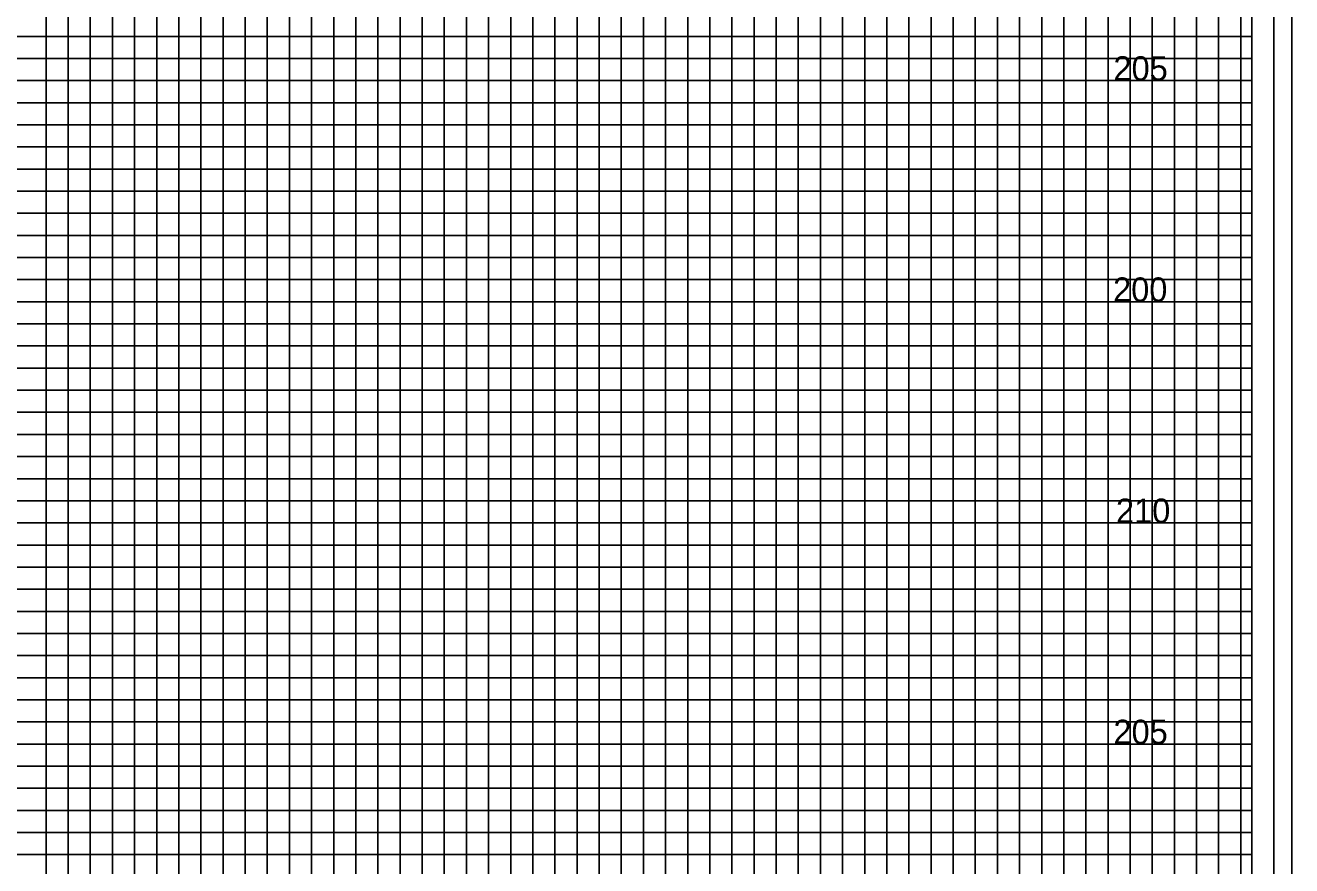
# Model space of a CAD drawing. Extents: x -4 to 103, y -2 to 67.
# Drawn here: x 74.78 to 103.4, y 32.25 to 51.25 of the extents above; entities that cross this region are included whole.
import ezdxf

# ---------------------------------------------------------------- set-up
doc = ezdxf.new("R2010")
doc.units = 0
for name, color, linetype in [('Old_Level_10', 7, 'Continuous'), ('Old_Level_17', 7, 'Continuous'), ('Old_Level_5', 7, 'Continuous'), ('Old_Level_8', 7, 'Continuous'), ('Prop Plan Preparation Sketches Hydraulic Ditch', 7, 'Continuous'), ('Prop XS Dump Level', 7, 'Continuous'), ('Prop XS Finish Grade Pavement', 7, 'Continuous')]:
    doc.layers.add(name, color=color, linetype=linetype)

msp = doc.modelspace()

# ---------------------------------------------------------------- linework, layer by layer
at = {"layer": 'Old_Level_10'}
for p, q in [((91.25, 0), (91.25, 63.425)), ((93.75, 0), (93.75, 63.425)), ((96.25, 0), (96.25, 63.425)), ((98.75, 0), (98.75, 63.425)), ((101.25, 0), (101.25, 63.425)), ((76.25, 0), (76.25, 62)), ((78.75, 0), (78.75, 62)), ((81.25, 0), (81.25, 62)), ((83.75, 0), (83.75, 62)), ((86.25, 0), (86.25, 62)), ((88.75, 0), (88.75, 62)), ((0, 50), (102.5, 50)), ((0, 47.5), (102.5, 47.5)), ((0, 45), (102.5, 45)), ((0, 42.5), (102.5, 42.5)), ((0, 40), (102.5, 40)), ((0, 37.5), (102.5, 37.5)), ((0, 35), (102.5, 35)), ((0, 32.5), (102.5, 32.5))]:
    msp.add_line(p, q, dxfattribs=at)
at = {"layer": 'Old_Level_17'}
msp.add_lwpolyline([(103, 66), (-2.8, 66), (-2.8, -1), (103, -1)], close=True, dxfattribs=at)
at = {"layer": 'Old_Level_5'}
msp.add_lwpolyline([(103.4, 67.4), (-3.5, 67.4), (-3.5, -2.425), (103.4, -2.425)], close=True, dxfattribs=at)
at = {"layer": 'Old_Level_8'}
for points in [[(91.25, 0), (91.25, 63.425), (93.75, 63.425), (93.75, 0)], [(96.25, 0), (96.25, 63.425), (98.75, 63.425), (98.75, 0)], [(101.25, 0), (101.25, 63.425)], [(76.25, 0), (76.25, 62), (78.75, 62), (78.75, 0)], [(81.25, 0), (81.25, 62), (83.75, 62), (83.75, 0)], [(86.25, 0), (86.25, 62), (88.75, 62), (88.75, 0)], [(0, 47.5), (102.5, 47.5), (102.5, 50), (0, 50)], [(0, 42.5), (102.5, 42.5), (102.5, 45), (0, 45)], [(0, 37.5), (102.5, 37.5), (102.5, 40), (0, 40)], [(0, 32.5), (102.5, 32.5), (102.5, 35), (0, 35)]]:
    msp.add_lwpolyline(points, dxfattribs=at)
at = {"layer": 'Prop Plan Preparation Sketches Hydraulic Ditch'}
msp.add_lwpolyline([(102.5, 65), (0, 65), (0, 0), (102.5, 0)], close=True, dxfattribs=at)
at = {"layer": 'Prop XS Dump Level'}
for points in [[(90.25, 0), (90.25, 63.425), (90.75, 63.425), (90.75, 0)], [(91.75, 0), (91.75, 63.425), (92.25, 63.425), (92.25, 0)], [(92.75, 0), (92.75, 63.425), (93.25, 63.425), (93.25, 0)], [(94.25, 0), (94.25, 63.425), (94.75, 63.425), (94.75, 0)], [(95.25, 0), (95.25, 63.425), (95.75, 63.425), (95.75, 0)], [(96.75, 0), (96.75, 63.425), (97.25, 63.425), (97.25, 0)], [(97.75, 0), (97.75, 63.425), (98.25, 63.425), (98.25, 0)], [(99.25, 0), (99.25, 63.425), (99.75, 63.425), (99.75, 0)], [(100.25, 0), (100.25, 63.425)], [(100.25, 63.425), (100.75, 63.425), (100.75, 0), (101.75, 0), (101.75, 63.425), (102.25, 63.425), (102.25, 0)], [(75.25, 0), (75.25, 62), (75.75, 62), (75.75, 0)], [(76.75, 0), (76.75, 62), (77.25, 62), (77.25, 0)], [(77.75, 0), (77.75, 62), (78.25, 62), (78.25, 0)], [(79.25, 0), (79.25, 62), (79.75, 62), (79.75, 0)], [(80.25, 0), (80.25, 62), (80.75, 62), (80.75, 0)], [(81.75, 0), (81.75, 62), (82.25, 62), (82.25, 0)], [(82.75, 0), (82.75, 62), (83.25, 62), (83.25, 0)], [(84.25, 0), (84.25, 62), (84.75, 62), (84.75, 0)], [(85.25, 0), (85.25, 62), (85.75, 62), (85.75, 0)], [(86.75, 0), (86.75, 62), (87.25, 62), (87.25, 0)], [(87.75, 0), (87.75, 62), (88.25, 62), (88.25, 0)], [(89.25, 0), (89.25, 62), (89.75, 62), (89.75, 0)], [(0, 50.5), (102.5, 50.5), (102.5, 51), (0, 51)], [(0, 49), (102.5, 49), (102.5, 49.5), (0, 49.5)], [(0, 48), (102.5, 48), (102.5, 48.5), (0, 48.5)], [(0, 46.5), (102.5, 46.5), (102.5, 47), (0, 47)], [(0, 45.5), (102.5, 45.5), (102.5, 46), (0, 46)], [(0, 44), (102.5, 44), (102.5, 44.5), (0, 44.5)], [(0, 43), (102.5, 43), (102.5, 43.5), (0, 43.5)], [(0, 41.5), (102.5, 41.5), (102.5, 42), (0, 42)], [(0, 40.5), (102.5, 40.5), (102.5, 41), (0, 41)], [(0, 39), (102.5, 39), (102.5, 39.5), (0, 39.5)], [(0, 38), (102.5, 38), (102.5, 38.5), (0, 38.5)], [(0, 36.5), (102.5, 36.5), (102.5, 37), (0, 37)], [(0, 35.5), (102.5, 35.5), (102.5, 36), (0, 36)], [(0, 34), (102.5, 34), (102.5, 34.5), (0, 34.5)], [(0, 33), (102.5, 33), (102.5, 33.5), (0, 33.5)]]:
    msp.add_lwpolyline(points, dxfattribs=at)

# ---------------------------------------------------------------- texts
at = {"layer": 'Prop XS Finish Grade Pavement'}
for s, p in [('205', (99.3724, 50)), ('200', (99.3638, 45)), ('210', (99.4296, 40)), ('205', (99.3724, 35))]:
    msp.add_text(s, height=0.55, dxfattribs=at).set_placement(p)

doc.saveas('drawing.dxf')
